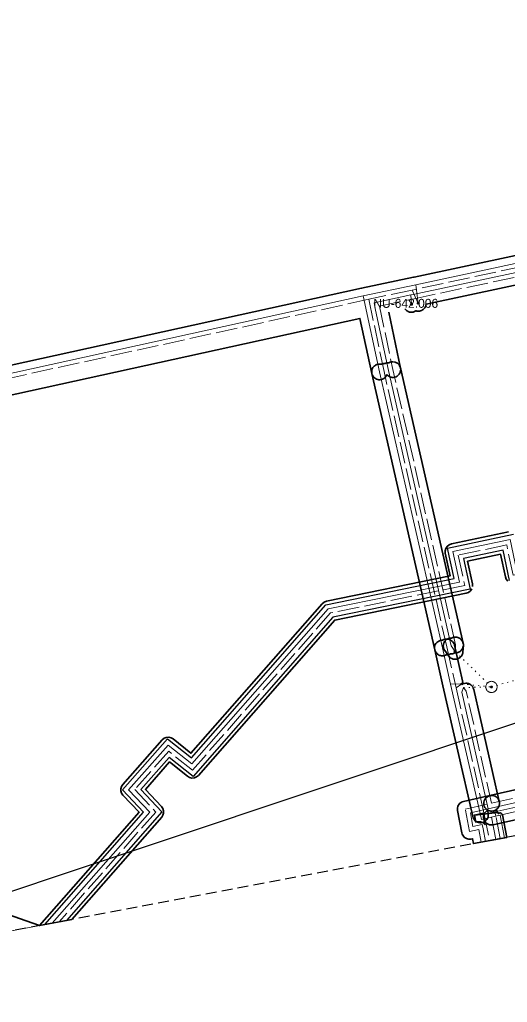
# Model space of a CAD drawing. Extents: x -452602 to -451136, y -1100088 to -1099653.
# Drawn here: x -452295.4 to -452252, y -1100042.4 to -1099954.9 of the extents above; entities that cross this region are included whole.
import ezdxf

# ---------------------------------------------------------------- set-up
doc = ezdxf.new("R2010")
doc.units = 0
doc.header["$LTSCALE"] = 0.32
doc.header["$PDMODE"] = 32
doc.header["$PDSIZE"] = 0.16
for name, pattern in [('DOTTED', [1.5, 0.3, -1.2]), ('LONG_DASHED', [7.5, 6, -1.5]), ('MEDIUM_DASHED', [4.5, 3, -1.5])]:
    doc.linetypes.add(name, pattern=pattern)
doc.layers.add('1', color=7, linetype='Continuous')
doc.layers.add('4', color=7, linetype='Continuous')
for name, color, linetype, lineweight in [('2', 7, 'Continuous', 13), ('3', 7, 'Continuous', 25), ('5', 7, 'Continuous', 13), ('62', 7, 'MEDIUM_DASHED', 25), ('8', 7, 'Continuous', 35)]:
    doc.layers.add(name, color=color, linetype=linetype, lineweight=lineweight)

msp = doc.modelspace()

# ---------------------------------------------------------------- linework, layer by layer
at = {"layer": '1'}
for p in [(-452256.662, -1100011.164), (-452256.061, -1100014.059)]:
    msp.add_point(p, dxfattribs=at)
at = {"layer": '2', "linetype": 'LONG_DASHED'}
for p, q in [((-452241.297, -1099974.845), (-452260.491, -1099978.95)), ((-452260.491, -1099978.95), (-452264.35, -1099979.776)), ((-452259.943, -1099980.137), (-452260.491, -1099978.95)), ((-452264.35, -1099979.776), (-452315.103, -1099990.927)), ((-452264.35, -1099979.776), (-452262.991, -1099986.21)), ((-452263.393, -1099980.389), (-452260.776, -1099979.829)), ((-452263.393, -1099980.389), (-452262.21, -1099986.043)), ((-452260.556, -1099980.233), (-452260.776, -1099979.829)), ((-452257.406, -1100010.76), (-452262.991, -1099986.21)), ((-452256.626, -1100010.587), (-452262.21, -1099986.043)), ((-452257.406, -1100010.76), (-452256.574, -1100014.412)), ((-452256.626, -1100010.587), (-452256.662, -1100011.164)), ((-452256.574, -1100014.412), (-452256.061, -1100014.059)), ((-452256.574, -1100014.412), (-452254.064, -1100025.653)), ((-452255.689, -1100014.697), (-452255.926, -1100014.372)), ((-452253.41, -1100024.697), (-452255.689, -1100014.697)), ((-452253.41, -1100024.697), (-452247.89, -1100023.439)), ((-452253.122, -1100025.448), (-452247.711, -1100024.27)), ((-452254.064, -1100025.653), (-452253.122, -1100025.448)), ((-452254.064, -1100025.653), (-452253.6, -1100028.024))]:
    msp.add_line(p, q, dxfattribs=at)
at = {"layer": '2'}
for p, q in [((-452242.089, -1099974.607), (-452260.167, -1099978.477)), ((-452260.167, -1099978.477), (-452264.85, -1099979.478)), ((-452260.167, -1099978.477), (-452259.943, -1099980.137)), ((-452264.85, -1099979.478), (-452316.457, -1099990.813)), ((-452264.85, -1099979.478), (-452263.393, -1099986.25)), ((-452260.591, -1099979.382), (-452263.866, -1099980.1)), ((-452260.591, -1099979.382), (-452260.556, -1099980.233)), ((-452257.795, -1100010.855), (-452263.393, -1099986.25)), ((-452257.016, -1100010.675), (-452262.6, -1099986.133)), ((-452257.795, -1100010.855), (-452257.062, -1100014.074)), ((-452257.016, -1100010.675), (-452256.662, -1100011.164)), ((-452257.062, -1100014.074), (-452254.405, -1100025.731)), ((-452257.061, -1100014.074), (-452256.061, -1100014.059)), ((-452255.926, -1100014.372), (-452256.077, -1100014.794)), ((-452256.077, -1100014.794), (-452253.711, -1100025.179)), ((-452253.711, -1100025.179), (-452247.801, -1100023.829)), ((-452252.652, -1100025.755), (-452247.634, -1100024.612)), ((-452253.431, -1100025.932), (-452252.652, -1100025.755)), ((-452253.046, -1100027.919), (-452253.431, -1100025.932)), ((-452252.261, -1100027.771), (-452252.652, -1100025.755))]:
    msp.add_line(p, q, dxfattribs=at)
at = {"layer": '2', "linetype": 'DOTTED'}
for p, q in [((-452253.424, -1100014.326), (-452256.662, -1100011.164)), ((-452255.926, -1100014.372), (-452253.424, -1100014.326))]:
    msp.add_line(p, q, dxfattribs=at)
at = {"layer": '2'}
for points in [[(-452241.127, -1099975.217), (-452241.213, -1099975.236), (-452260.407, -1099979.341), (-452260.591, -1099979.382)], [(-452262.6, -1099986.133), (-452263.744, -1099980.736), (-452263.866, -1099980.1)], [(-452230.97, -1100011.922), (-452233.825, -1100000.337), (-452251.193, -1100003.897), (-452251.762, -1100001.19), (-452256.853, -1100002.269), (-452256.282, -1100004.975), (-452267.969, -1100007.37), (-452280.097, -1100021.193), (-452282.212, -1100019.502), (-452285.734, -1100023.486), (-452283.859, -1100025.484), (-452292.551, -1100035.39), (-452319.689, -1100040.522), (-452321.428, -1100031.934), (-452361.009, -1100040.625), (-452368.273, -1100005.285), (-452374.31, -1100006.761), (-452374.659, -1100007.061)], [(-452253.946, -1100028.089), (-452254.166, -1100026.961), (-452254.254, -1100026.586), (-452255.085, -1100026.75), (-452255.302, -1100025.534), (-452253.711, -1100025.179)], [(-452254.405, -1100025.731), (-452254.314, -1100026.133), (-452253.431, -1100025.932)]]:
    msp.add_lwpolyline(points, dxfattribs=at)
at = {"layer": '2', "linetype": 'LONG_DASHED'}
for points in [[(-452260.776, -1099979.829), (-452260.323, -1099979.732), (-452241.13, -1099975.627), (-452240.728, -1099975.541)], [(-452231.354, -1100012.033), (-452234.13, -1100000.807), (-452251.502, -1100004.37), (-452252.071, -1100001.664), (-452256.379, -1100002.578), (-452255.809, -1100005.287), (-452267.758, -1100007.734), (-452280.049, -1100021.745), (-452282.164, -1100020.052), (-452285.193, -1100023.478), (-452283.32, -1100025.473), (-452291.913, -1100035.269), (-452320.083, -1100040.596), (-452321.74, -1100032.412), (-452361.32, -1100041.103), (-452368.581, -1100005.774), (-452374.217, -1100007.149), (-452374.659, -1100007.061)], [(-452254.339, -1100028.164), (-452254.559, -1100027.036), (-452255.368, -1100027.201), (-452255.765, -1100025.216), (-452253.41, -1100024.697)], [(-452252.653, -1100027.845), (-452253.038, -1100025.856), (-452253.122, -1100025.448)]]:
    msp.add_lwpolyline(points, dxfattribs=at)
at = {"layer": '2', "linetype": 'DOTTED'}
msp.add_lwpolyline([(-452256.061, -1100014.059), (-452253.424, -1100014.326), (-452250.049, -1100013.363)], dxfattribs=at)
at = {"layer": '3'}
for points in [[(-452251.812, -1100004.841), (-452252.38, -1100002.138), (-452255.905, -1100002.886), (-452255.334, -1100005.598), (-452267.545, -1100008.099), (-452280, -1100022.297), (-452282.117, -1100020.603), (-452284.652, -1100023.469), (-452282.78, -1100025.464), (-452291.275, -1100035.149), (-452293.188, -1100035.51), (-452284.4, -1100025.493), (-452286.276, -1100023.493), (-452282.26, -1100018.952), (-452280.145, -1100020.642), (-452268.181, -1100007.006), (-452256.757, -1100004.663), (-452257.326, -1100001.961), (-452251.453, -1100000.715)], [(-452231.993, -1100011.115), (-452320.476, -1100040.671)]]:
    msp.add_lwpolyline(points, dxfattribs=at)
at = {"layer": '4'}
for p in [(-452260.556, -1099980.233), (-452259.943, -1099980.137)]:
    msp.add_point(p, dxfattribs=at)
at = {"layer": '5'}
for points in [[(-452252.924, -1100014.326), (-452252.927, -1100014.274), (-452252.935, -1100014.221), (-452252.949, -1100014.171), (-452252.967, -1100014.123), (-452252.991, -1100014.076), (-452253.02, -1100014.032), (-452253.053, -1100013.991), (-452253.09, -1100013.954), (-452253.13, -1100013.921), (-452253.174, -1100013.893), (-452253.221, -1100013.869), (-452253.27, -1100013.85), (-452253.32, -1100013.836), (-452253.372, -1100013.829), (-452253.424, -1100013.826), (-452253.476, -1100013.829), (-452253.528, -1100013.836), (-452253.579, -1100013.85), (-452253.627, -1100013.869), (-452253.674, -1100013.893), (-452253.718, -1100013.921), (-452253.759, -1100013.954), (-452253.796, -1100013.991), (-452253.829, -1100014.032), (-452253.857, -1100014.076), (-452253.881, -1100014.123), (-452253.9, -1100014.171), (-452253.913, -1100014.221), (-452253.921, -1100014.274), (-452253.924, -1100014.326), (-452253.921, -1100014.377), (-452253.913, -1100014.43), (-452253.9, -1100014.481), (-452253.881, -1100014.528), (-452253.857, -1100014.576), (-452253.829, -1100014.619), (-452253.796, -1100014.66), (-452253.759, -1100014.697), (-452253.718, -1100014.731), (-452253.674, -1100014.758), (-452253.627, -1100014.782), (-452253.579, -1100014.802), (-452253.528, -1100014.815), (-452253.476, -1100014.822), (-452253.424, -1100014.826), (-452253.372, -1100014.822), (-452253.32, -1100014.815), (-452253.27, -1100014.802), (-452253.221, -1100014.782), (-452253.174, -1100014.758), (-452253.13, -1100014.731), (-452253.09, -1100014.697), (-452253.053, -1100014.66), (-452253.02, -1100014.619), (-452252.991, -1100014.576), (-452252.967, -1100014.528), (-452252.949, -1100014.481), (-452252.935, -1100014.43), (-452252.927, -1100014.377)], [(-452253.342, -1100014.326), (-452253.342, -1100014.316), (-452253.344, -1100014.309), (-452253.346, -1100014.301), (-452253.349, -1100014.292), (-452253.353, -1100014.285), (-452253.358, -1100014.278), (-452253.363, -1100014.271), (-452253.369, -1100014.265), (-452253.376, -1100014.259), (-452253.383, -1100014.255), (-452253.391, -1100014.251), (-452253.399, -1100014.248), (-452253.407, -1100014.245), (-452253.415, -1100014.244), (-452253.424, -1100014.244), (-452253.433, -1100014.244), (-452253.441, -1100014.245), (-452253.449, -1100014.248), (-452253.457, -1100014.251), (-452253.465, -1100014.255), (-452253.472, -1100014.259), (-452253.479, -1100014.265), (-452253.485, -1100014.271), (-452253.491, -1100014.278), (-452253.495, -1100014.285), (-452253.499, -1100014.292), (-452253.502, -1100014.301), (-452253.504, -1100014.309), (-452253.506, -1100014.316), (-452253.506, -1100014.326), (-452253.506, -1100014.335), (-452253.504, -1100014.342), (-452253.502, -1100014.35), (-452253.499, -1100014.359), (-452253.495, -1100014.366), (-452253.491, -1100014.373), (-452253.485, -1100014.38), (-452253.479, -1100014.386), (-452253.472, -1100014.393), (-452253.465, -1100014.397), (-452253.457, -1100014.4), (-452253.449, -1100014.403), (-452253.441, -1100014.406), (-452253.433, -1100014.407), (-452253.424, -1100014.407), (-452253.415, -1100014.407), (-452253.407, -1100014.406), (-452253.399, -1100014.403), (-452253.391, -1100014.4), (-452253.383, -1100014.397), (-452253.376, -1100014.393), (-452253.369, -1100014.386), (-452253.363, -1100014.38), (-452253.358, -1100014.373), (-452253.353, -1100014.366), (-452253.349, -1100014.359), (-452253.346, -1100014.35), (-452253.344, -1100014.342), (-452253.342, -1100014.335)]]:
    msp.add_lwpolyline(points, close=True, dxfattribs=at)
at = {"layer": '62'}
msp.add_lwpolyline([(-451137.485, -1099816.961), (-452572.169, -1100088.267), (-452602.314, -1099919.678), (-451137.485, -1099652.838), (-451136.368, -1099701.963)], close=True, dxfattribs=at)
at = {"layer": '8'}
for points in [[(-452316.607, -1099990.13), (-452265, -1099978.795), (-452264.995, -1099978.794), (-452260.355, -1099977.801), (-452260.315, -1099977.792), (-452260.305, -1099977.79), (-452242.27, -1099973.931)], [(-452241.891, -1099976.506), (-452259.248, -1099980.218), (-452259.249, -1099980.228), (-452259.257, -1099980.274), (-452259.267, -1099980.318), (-452259.281, -1099980.362), (-452259.297, -1099980.405), (-452259.316, -1099980.447), (-452259.337, -1099980.487), (-452259.361, -1099980.526), (-452259.388, -1099980.563), (-452259.417, -1099980.598), (-452259.448, -1099980.632), (-452259.482, -1099980.663), (-452259.517, -1099980.692), (-452259.554, -1099980.719), (-452259.593, -1099980.743), (-452259.634, -1099980.765), (-452259.675, -1099980.784), (-452259.718, -1099980.8), (-452259.762, -1099980.813), (-452259.807, -1099980.823), (-452259.852, -1099980.831), (-452259.898, -1099980.835), (-452259.943, -1099980.837), (-452259.989, -1099980.835), (-452260.035, -1099980.831), (-452260.08, -1099980.823), (-452260.125, -1099980.813), (-452260.153, -1099980.804), (-452260.167, -1099980.815), (-452260.206, -1099980.839), (-452260.247, -1099980.861), (-452260.288, -1099980.879), (-452260.331, -1099980.896), (-452260.375, -1099980.909), (-452260.42, -1099980.919), (-452260.465, -1099980.927), (-452260.51, -1099980.931), (-452260.556, -1099980.933), (-452260.602, -1099980.931), (-452260.648, -1099980.927), (-452260.693, -1099980.919), (-452260.737, -1099980.909), (-452260.781, -1099980.896), (-452260.824, -1099980.879), (-452260.866, -1099980.861), (-452260.906, -1099980.839), (-452260.945, -1099980.815), (-452260.982, -1099980.788), (-452261.018, -1099980.759), (-452261.051, -1099980.728), (-452261.082, -1099980.694), (-452261.111, -1099980.659), (-452261.138, -1099980.622)], [(-452262.565, -1099980.928), (-452261.524, -1099985.9), (-452261.51, -1099986.018), (-452261.516, -1099986.136), (-452261.541, -1099986.252), (-452261.586, -1099986.362), (-452261.649, -1099986.463), (-452261.728, -1099986.552), (-452261.821, -1099986.626), (-452261.924, -1099986.683), (-452262.037, -1099986.722), (-452262.154, -1099986.741), (-452262.263, -1099986.741), (-452262.371, -1099986.725), (-452262.475, -1099986.691), (-452262.573, -1099986.642), (-452262.662, -1099986.578), (-452262.74, -1099986.501), (-452262.788, -1099986.602), (-452262.852, -1099986.694), (-452262.93, -1099986.775), (-452263.02, -1099986.842), (-452263.12, -1099986.894), (-452263.226, -1099986.93), (-452263.337, -1099986.948), (-452263.449, -1099986.948), (-452263.559, -1099986.93), (-452263.665, -1099986.895), (-452263.765, -1099986.843), (-452263.854, -1099986.776), (-452263.932, -1099986.696), (-452263.996, -1099986.605), (-452264.045, -1099986.504), (-452264.077, -1099986.397), (-452265.134, -1099981.484), (-452313.559, -1099992.123)], [(-452261.87, -1099985.431), (-452261.807, -1099985.471), (-452261.748, -1099985.517), (-452261.695, -1099985.569), (-452261.648, -1099985.626), (-452261.606, -1099985.688), (-452261.572, -1099985.754), (-452261.545, -1099985.824), (-452261.527, -1099985.888), (-452255.943, -1100010.432), (-452255.941, -1100010.44), (-452255.929, -1100010.513), (-452255.925, -1100010.587), (-452255.929, -1100010.662), (-452255.941, -1100010.736), (-452255.961, -1100010.807), (-452255.988, -1100010.877), (-452256.022, -1100010.943), (-452256.064, -1100011.005), (-452256.111, -1100011.062), (-452256.164, -1100011.114), (-452256.223, -1100011.16), (-452256.286, -1100011.2), (-452256.353, -1100011.232), (-452256.423, -1100011.258), (-452256.496, -1100011.275), (-452256.57, -1100011.285), (-452256.644, -1100011.287), (-452256.672, -1100011.285), (-452256.676, -1100011.288), (-452256.743, -1100011.32), (-452256.813, -1100011.346), (-452256.886, -1100011.363), (-452256.96, -1100011.373), (-452257.034, -1100011.375), (-452257.068, -1100011.372), (-452257.134, -1100011.404), (-452257.204, -1100011.43), (-452257.277, -1100011.447), (-452257.351, -1100011.457), (-452257.425, -1100011.459), (-452257.442, -1100011.458), (-452257.456, -1100011.467), (-452257.523, -1100011.499), (-452257.593, -1100011.525), (-452257.666, -1100011.542), (-452257.74, -1100011.552), (-452257.814, -1100011.554), (-452257.888, -1100011.548), (-452257.962, -1100011.535), (-452258.033, -1100011.513), (-452258.102, -1100011.484), (-452258.167, -1100011.448), (-452258.228, -1100011.405), (-452258.284, -1100011.356), (-452258.334, -1100011.301), (-452258.379, -1100011.241), (-452258.417, -1100011.177), (-452258.447, -1100011.109), (-452258.471, -1100011.039), (-452258.478, -1100011.01), (-452264.076, -1099986.405), (-452264.084, -1099986.361), (-452264.092, -1099986.287), (-452264.092, -1099986.213), (-452264.084, -1099986.139), (-452264.068, -1099986.066), (-452264.045, -1099985.995), (-452264.014, -1099985.927), (-452263.976, -1099985.863), (-452263.932, -1099985.803), (-452263.881, -1099985.749), (-452263.825, -1099985.699), (-452263.764, -1099985.657), (-452263.699, -1099985.62), (-452263.63, -1099985.592), (-452263.559, -1099985.57), (-452263.486, -1099985.556), (-452263.412, -1099985.55), (-452263.337, -1099985.552), (-452263.263, -1099985.562), (-452263.257, -1099985.564), (-452263.229, -1099985.552), (-452263.158, -1099985.53), (-452263.084, -1099985.517), (-452263.01, -1099985.511), (-452262.936, -1099985.513), (-452262.926, -1099985.514), (-452262.906, -1099985.503), (-452262.837, -1099985.474), (-452262.766, -1099985.453), (-452262.692, -1099985.439), (-452262.618, -1099985.433), (-452262.553, -1099985.434), (-452262.516, -1099985.414), (-452262.447, -1099985.385), (-452262.376, -1099985.364), (-452262.302, -1099985.35), (-452262.228, -1099985.344), (-452262.154, -1099985.346)], [(-452262.08, -1099985.356), (-452262.007, -1099985.373), (-452261.937, -1099985.399), (-452261.87, -1099985.431)], [(-452374.913, -1100007.111), (-452293.667, -1100035.601), (-452284.805, -1100025.499), (-452286.245, -1100023.964), (-452286.362, -1100023.795), (-452286.425, -1100023.599), (-452286.428, -1100023.393), (-452286.371, -1100023.195), (-452286.259, -1100023.022), (-452282.737, -1100019.039), (-452282.574, -1100018.903), (-452282.378, -1100018.822), (-452282.166, -1100018.804), (-452281.959, -1100018.85), (-452281.776, -1100018.956), (-452280.182, -1100020.229), (-452268.496, -1100006.909), (-452268.321, -1100006.765), (-452268.11, -1100006.685), (-452257.113, -1100004.43), (-452257.538, -1100002.414), (-452257.549, -1100002.195), (-452257.492, -1100001.984), (-452257.372, -1100001.801), (-452257.202, -1100001.663), (-452256.998, -1100001.585), (-452251.907, -1100000.505)], [(-452251.973, -1100004.888), (-452252.11, -1100004.718), (-452252.188, -1100004.513), (-452252.612, -1100002.494), (-452255.55, -1100003.117), (-452255.123, -1100005.142), (-452255.113, -1100005.362)], [(-452255.17, -1100005.574), (-452255.291, -1100005.758), (-452255.462, -1100005.895), (-452255.668, -1100005.972), (-452267.387, -1100008.373), (-452279.522, -1100022.207), (-452279.685, -1100022.344), (-452279.882, -1100022.425), (-452280.094, -1100022.444), (-452280.301, -1100022.398), (-452280.486, -1100022.292), (-452282.082, -1100021.015), (-452284.246, -1100023.464), (-452282.809, -1100024.995), (-452282.692, -1100025.163), (-452282.629, -1100025.359), (-452282.626, -1100025.565), (-452282.682, -1100025.762), (-452282.793, -1100025.935), (-452290.797, -1100035.058), (-452293.667, -1100035.601)], [(-452247.478, -1100025.294), (-452253.275, -1100026.615), (-452253.301, -1100026.62), (-452253.375, -1100026.63), (-452253.495, -1100026.63), (-452253.613, -1100026.608), (-452253.726, -1100026.567), (-452253.83, -1100026.508), (-452253.923, -1100026.431), (-452254, -1100026.339), (-452254.062, -1100026.236), (-452254.104, -1100026.124), (-452254.127, -1100026.006), (-452254.129, -1100025.886), (-452254.111, -1100025.767), (-452254.072, -1100025.653), (-452254.015, -1100025.547), (-452253.941, -1100025.453), (-452253.851, -1100025.373), (-452253.749, -1100025.309), (-452253.849, -1100025.242), (-452253.936, -1100025.159), (-452254.008, -1100025.062), (-452254.061, -1100024.954), (-452254.096, -1100024.839), (-452254.11, -1100024.719), (-452254.103, -1100024.599), (-452254.076, -1100024.481), (-452254.029, -1100024.37), (-452253.964, -1100024.269), (-452253.883, -1100024.18), (-452253.787, -1100024.107), (-452253.68, -1100024.051), (-452253.566, -1100024.014), (-452248.046, -1100022.757)], [(-452252.867, -1100025.522), (-452252.812, -1100025.608), (-452252.804, -1100025.627), (-452252.78, -1100025.602), (-452252.751, -1100025.582), (-452252.72, -1100025.568), (-452252.687, -1100025.559), (-452252.653, -1100025.556), (-452252.618, -1100025.559), (-452252.585, -1100025.567), (-452252.553, -1100025.581), (-452252.525, -1100025.601), (-452252.5, -1100025.625), (-452252.48, -1100025.653), (-452252.465, -1100025.684), (-452252.455, -1100025.717), (-452252.065, -1100027.734), (-452255.027, -1100028.294), (-452255.111, -1100027.863), (-452255.228, -1100027.886), (-452255.337, -1100027.9), (-452255.447, -1100027.896), (-452255.555, -1100027.875), (-452255.659, -1100027.837), (-452255.755, -1100027.784), (-452255.842, -1100027.716), (-452255.917, -1100027.635), (-452255.978, -1100027.544), (-452256.024, -1100027.444), (-452256.054, -1100027.338), (-452256.451, -1100025.353), (-452256.464, -1100025.234), (-452256.457, -1100025.114), (-452256.429, -1100024.996), (-452256.381, -1100024.886), (-452256.316, -1100024.785), (-452256.233, -1100024.697), (-452256.137, -1100024.624), (-452256.03, -1100024.569), (-452255.915, -1100024.533), (-452253.561, -1100024.013), (-452253.443, -1100023.998), (-452253.324, -1100024.002), (-452253.208, -1100024.027), (-452253.097, -1100024.071), (-452252.995, -1100024.133), (-452252.906, -1100024.211), (-452252.831, -1100024.304), (-452252.773, -1100024.408), (-452252.733, -1100024.52), (-452252.713, -1100024.637), (-452252.713, -1100024.756), (-452252.733, -1100024.874), (-452252.773, -1100024.986), (-452252.831, -1100025.09), (-452252.906, -1100025.182), (-452252.995, -1100025.261), (-452253.023, -1100025.278), (-452252.996, -1100025.296), (-452252.972, -1100025.32), (-452252.952, -1100025.346), (-452252.937, -1100025.376), (-452252.927, -1100025.408), (-452252.914, -1100025.467), (-452252.867, -1100025.522), (-452254.943, -1100025.752), (-452254.819, -1100026.375), (-452254.698, -1100026.35), (-452254.59, -1100026.337), (-452254.481, -1100026.34), (-452254.375, -1100026.361), (-452254.272, -1100026.397), (-452254.177, -1100026.449), (-452254.09, -1100026.516), (-452254.015, -1100026.595), (-452254.118, -1100026.066), (-452254.129, -1100025.957), (-452254.123, -1100025.849), (-452254.101, -1100025.742), (-452254.062, -1100025.64), (-452254.009, -1100025.546), (-452254.943, -1100025.752)]]:
    msp.add_lwpolyline(points, dxfattribs=at)
for points in [[(-452256.724, -1100010.604), (-452255.941, -1100014.04), (-452255.826, -1100014.007), (-452255.706, -1100013.994), (-452255.586, -1100014.001), (-452255.469, -1100014.029), (-452255.359, -1100014.076), (-452255.258, -1100014.142), (-452255.17, -1100014.224), (-452255.098, -1100014.32), (-452255.043, -1100014.427), (-452255.006, -1100014.541), (-452252.728, -1100024.541), (-452252.711, -1100024.66), (-452252.715, -1100024.78), (-452252.74, -1100024.897), (-452252.784, -1100025.009), (-452252.846, -1100025.111), (-452252.925, -1100025.201), (-452253.018, -1100025.277), (-452253.123, -1100025.335), (-452253.236, -1100025.375), (-452253.354, -1100025.395), (-452253.468, -1100025.394), (-452253.58, -1100025.376), (-452253.688, -1100025.339), (-452253.789, -1100025.286), (-452253.723, -1100025.575), (-452253.706, -1100025.694), (-452253.71, -1100025.814), (-452253.734, -1100025.931), (-452253.779, -1100026.043), (-452253.841, -1100026.145), (-452253.92, -1100026.236), (-452254.013, -1100026.311), (-452254.118, -1100026.369), (-452254.231, -1100026.409), (-452254.349, -1100026.429), (-452254.46, -1100026.429), (-452254.57, -1100026.411), (-452254.675, -1100026.377), (-452254.774, -1100026.326), (-452254.863, -1100026.261), (-452254.941, -1100026.182), (-452255.005, -1100026.091), (-452255.055, -1100025.992), (-452255.088, -1100025.886), (-452257.744, -1100014.229), (-452258.478, -1100011.01), (-452258.494, -1100010.895), (-452258.49, -1100010.78), (-452258.468, -1100010.666), (-452258.427, -1100010.557), (-452258.369, -1100010.457), (-452258.295, -1100010.368), (-452258.207, -1100010.293), (-452258.108, -1100010.232), (-452258.001, -1100010.189), (-452257.888, -1100010.164), (-452257.772, -1100010.158), (-452257.664, -1100010.105), (-452257.548, -1100010.07), (-452257.428, -1100010.056), (-452257.308, -1100010.063), (-452257.19, -1100010.09), (-452257.079, -1100010.138), (-452256.978, -1100010.203), (-452256.889, -1100010.285), (-452256.816, -1100010.382), (-452256.76, -1100010.489)], [(-452256.286, -1100009.975), (-452256.223, -1100010.015), (-452256.164, -1100010.061), (-452256.111, -1100010.113), (-452256.064, -1100010.17), (-452256.022, -1100010.232), (-452255.988, -1100010.298), (-452255.961, -1100010.368), (-452255.941, -1100010.44), (-452255.929, -1100010.513), (-452255.925, -1100010.587), (-452255.927, -1100010.632), (-452255.964, -1100011.208), (-452255.966, -1100011.238), (-452255.978, -1100011.311), (-452255.998, -1100011.383), (-452256.025, -1100011.453), (-452256.059, -1100011.519), (-452256.101, -1100011.581), (-452256.148, -1100011.638), (-452256.201, -1100011.69), (-452256.26, -1100011.736), (-452256.323, -1100011.776), (-452256.39, -1100011.808), (-452256.46, -1100011.834), (-452256.533, -1100011.851), (-452256.607, -1100011.861), (-452256.681, -1100011.863), (-452256.755, -1100011.857), (-452256.829, -1100011.844), (-452256.9, -1100011.822), (-452256.968, -1100011.793), (-452257.034, -1100011.757), (-452257.095, -1100011.714), (-452257.151, -1100011.665), (-452257.201, -1100011.61), (-452257.229, -1100011.574), (-452257.583, -1100011.086), (-452257.599, -1100011.063), (-452257.637, -1100010.998), (-452257.667, -1100010.93), (-452257.691, -1100010.86), (-452257.707, -1100010.787), (-452257.715, -1100010.713), (-452257.715, -1100010.638), (-452257.707, -1100010.564), (-452257.691, -1100010.491), (-452257.667, -1100010.421), (-452257.637, -1100010.353), (-452257.599, -1100010.289), (-452257.554, -1100010.229), (-452257.504, -1100010.174), (-452257.448, -1100010.125), (-452257.387, -1100010.082), (-452257.322, -1100010.046), (-452257.253, -1100010.017), (-452257.182, -1100009.995), (-452257.108, -1100009.982), (-452257.034, -1100009.976), (-452256.967, -1100009.978), (-452256.932, -1100009.958), (-452256.863, -1100009.929), (-452256.792, -1100009.907), (-452256.718, -1100009.894), (-452256.644, -1100009.888), (-452256.57, -1100009.89), (-452256.496, -1100009.9), (-452256.423, -1100009.917), (-452256.353, -1100009.943)]]:
    msp.add_lwpolyline(points, close=True, dxfattribs=at)

# ---------------------------------------------------------------- texts
at = {"layer": '4'}
msp.add_text('NU-642.006', height=0.8, dxfattribs=at).set_placement((-452263.943, -1099980.537))

doc.saveas('drawing.dxf')
